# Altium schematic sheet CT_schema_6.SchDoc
size 287 x 160 mm
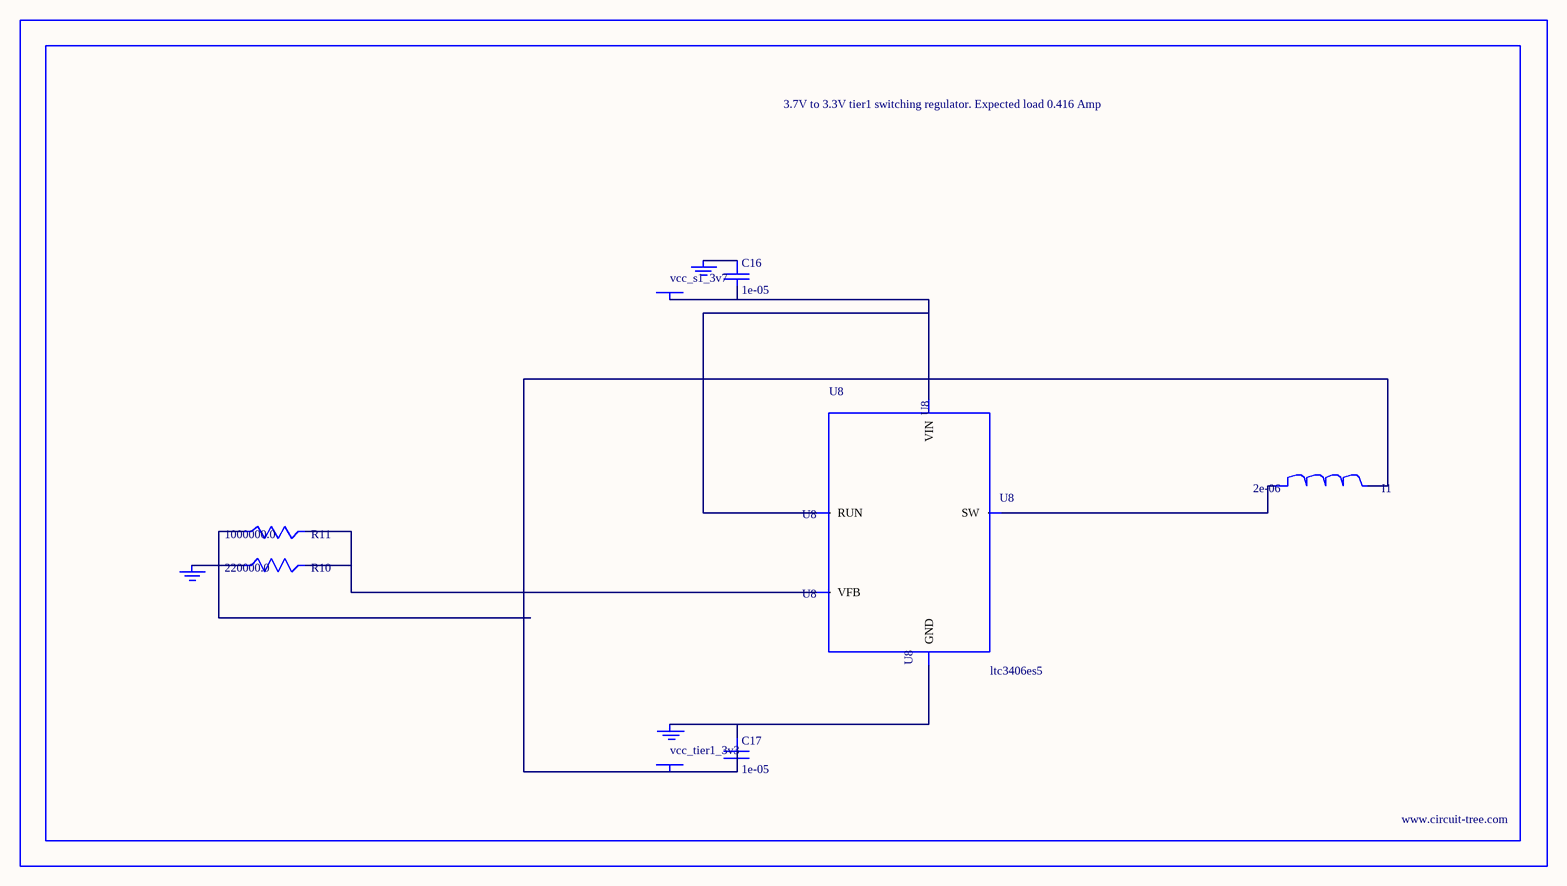
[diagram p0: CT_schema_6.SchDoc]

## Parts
BORDER5  (no value)
C16  1e-05  [C0805]
C17  1e-05  [C0805]
GND_INSTANCE_5_0  (no value)
GND_INSTANCE_5_1  (no value)
GND_INSTANCE_5_2  (no value)
I1  2e-06  [WE-HCI_7030/7040/7050]
POWER_INSTANCE_5_0  vcc_tier1_3v3
POWER_INSTANCE_5_1  vcc_s1_3v7
R10  220000.0  [R0603]
R11  1000000.0  [R0603]
U8  ltc3406es5  [TSOT-23-5]

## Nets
NetC16_1: C16.1 GND_INSTANCE_5_1.0(GND)
NetC16_2: C16.2 POWER_INSTANCE_5_1.0(PWR) U8.1(RUN) U8.4(VIN)
NetC17_1: C17.1 GND_INSTANCE_5_0.0(GND) U8.2(GND)
NetC17_2: C17.2 I1.2 POWER_INSTANCE_5_0.0(PWR) R11.1
NetGND_INSTANCE_5_2_0: GND_INSTANCE_5_2.0(GND) R10.1
NetI1_1: I1.1 U8.3(SW)
NetR10_2: R10.2 R11.2 U8.5(VFB)

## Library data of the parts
BORDER5 = BORDER_PAGE5
C16 C17 = C0805C106K8RACTU
GND_INSTANCE_5_0-GND_INSTANCE_5_2 = GND
I1 = 744314200
POWER_INSTANCE_5_0 POWER_INSTANCE_5_1 = PWR
R10 = RC0603JR-07220KL
R11 = RC0603JR-071ML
